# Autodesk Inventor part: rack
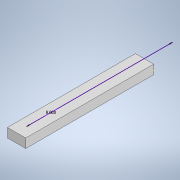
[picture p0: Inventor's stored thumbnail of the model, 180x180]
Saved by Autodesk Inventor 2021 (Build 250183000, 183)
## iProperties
Created: 2021-07
Part Number: rack
Material: Generic
Document SubType Name: Modeling
Designer: adams
Density: 1 g/cm^3
Appearance: Default
Author: adams
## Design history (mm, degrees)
sketch "Sketch2"
  geometry: L1 (-13.372, 7.111)-(12.028, 7.111); L2 (12.028, 7.111)-(12.028, -5.589); L3 (12.028, -5.589)-(-13.372, -5.589); L4 (-13.372, -5.589)-(-13.372, 7.111); 1 further point
  constraints: 8 end point, 2 parallel, 1 horizontal, 1 perpendicular
  dimensions: "d4" = 25.4 distance of L1.start L1.end; "d5" = 12.7 distance of L3.end L1.start
extrude "Extrusion2" new body sketch "Sketch2" distance "d6" = 177.8; taper "d7" = 0 deg
sketch "Sketch3"
  geometry: L1 (-176.983, 26.224)-(26.217, 26.224); 1 further point
  constraints: 2 end point, 1 horizontal
  dimensions: "d8" = 203.2 distance of L1.start L1.end
body "Solid2"
